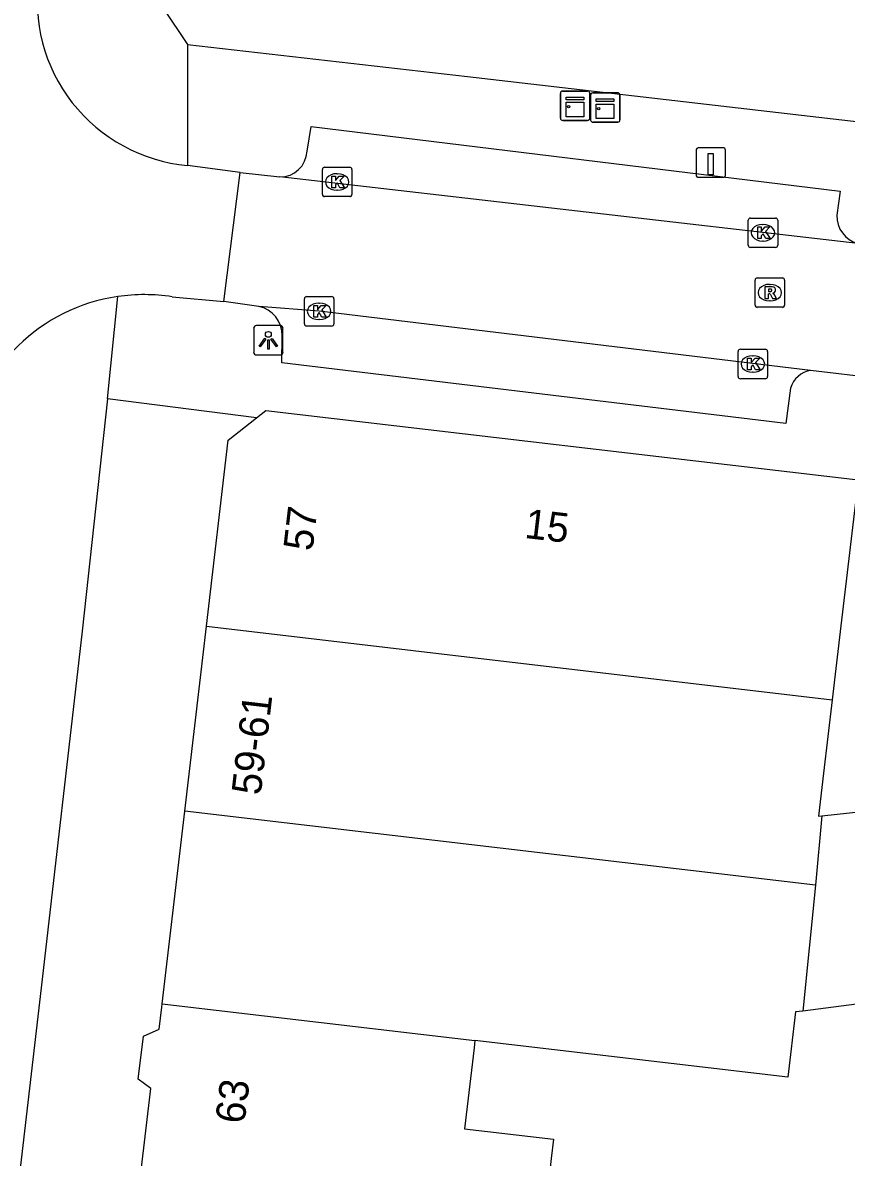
# Model space of a CAD drawing. Extents: x 162250 to 162654, y 380744 to 381605.
# Drawn here: x 162325.5 to 162353.49, y 381336.67 to 381375.24 of the extents above; entities that cross this region are included whole.
import ezdxf

# ---------------------------------------------------------------- set-up
doc = ezdxf.new("R2010")
doc.units = 0
for name, color, linetype in [('IMGEO_Kast', 7, 'Continuous'), ('IMGEO_Kolk', 7, 'Continuous'), ('IMGEO_Laadpaal', 7, 'Continuous'), ('IMGEO_Lichtpunt', 7, 'Continuous'), ('IMGEO_Pand', 7, 'Continuous'), ('IMGEO_Pand_nummerreeks', 7, 'Continuous'), ('IMGEO_Rijbaan_lokaal_open', 7, 'Continuous'), ('IMGEO_Rioolput', 7, 'Continuous'), ('IMGEO_Voetpad_open', 7, 'Continuous')]:
    doc.layers.add(name, color=color, linetype=linetype)

msp = doc.modelspace()

# ---------------------------------------------------------------- linework, layer by layer
at = {"layer": 'IMGEO_Kast'}
for p, q in [((162343.849, 381372.916), (162344.69, 381372.916)), ((162344.69, 381372.916), (162343.849, 381372.916)), ((162343.774, 381371.991), (162343.774, 381372.832)), ((162343.774, 381372.832), (162343.774, 381371.991)), ((162344.774, 381372.841), (162344.774, 381372)), ((162344.774, 381372), (162344.774, 381372.841)), ((162344.799, 381371.93), (162344.799, 381372.771)), ((162344.799, 381372.771), (162344.799, 381371.93)), ((162344.874, 381372.855), (162345.715, 381372.855)), ((162345.715, 381372.855), (162344.874, 381372.855)), ((162345.799, 381372.78), (162345.799, 381371.939)), ((162345.799, 381371.939), (162345.799, 381372.78)), ((162344.699, 381371.916), (162343.858, 381371.916)), ((162343.858, 381371.916), (162344.699, 381371.916)), ((162345.724, 381371.855), (162344.883, 381371.855)), ((162344.883, 381371.855), (162345.724, 381371.855))]:
    msp.add_line(p, q, dxfattribs=at)
for points in [[(162343.969, 381372.706), (162344.569, 381372.706), (162344.569, 381372.621), (162343.969, 381372.621), (162343.969, 381372.706)], [(162343.969, 381372.531), (162344.569, 381372.531), (162344.569, 381372.042), (162343.969, 381372.042), (162343.969, 381372.531)], [(162344.994, 381372.645), (162345.594, 381372.645), (162345.594, 381372.56), (162344.994, 381372.56), (162344.994, 381372.645)], [(162344.994, 381372.47), (162345.594, 381372.47), (162345.594, 381371.981), (162344.994, 381371.981), (162344.994, 381372.47)]]:
    msp.add_lwpolyline(points, dxfattribs=at)
for centre in [(162344.053, 381372.38), (162345.078, 381372.319)]:
    msp.add_circle(centre, 0.0377, dxfattribs=at)
for centre, start, end in [((162343.852, 381372.838), 92.4484, 184.2845), ((162343.852, 381372.838), 92.4484, 184.2845), ((162344.696, 381372.838), 2.4484, 94.2845), ((162344.696, 381372.838), 2.4484, 94.2845), ((162344.877, 381372.777), 92.4484, 184.2845), ((162344.877, 381372.777), 92.4484, 184.2845), ((162345.721, 381372.777), 2.4484, 94.2845), ((162345.721, 381372.777), 2.4484, 94.2845), ((162343.852, 381371.994), 182.4484, 274.2845), ((162343.852, 381371.994), 182.4484, 274.2845), ((162344.696, 381371.994), 272.4484, 4.2845), ((162344.696, 381371.994), 272.4484, 4.2845), ((162344.877, 381371.933), 182.4484, 274.2845), ((162344.877, 381371.933), 182.4484, 274.2845), ((162345.721, 381371.933), 272.4484, 4.2845), ((162345.721, 381371.933), 272.4484, 4.2845)]:
    msp.add_arc(centre, 0.0779, start, end, dxfattribs=at)
at = {"layer": 'IMGEO_Kolk'}
for p, q in [((162335.688, 381369.399), (162335.688, 381370.251)), ((162335.763, 381370.325), (162336.615, 381370.325)), ((162336.689, 381370.251), (162336.689, 381369.399)), ((162336.176, 381370.105), (162336.201, 381370.105)), ((162336.199, 381369.545), (162336.174, 381369.545)), ((162336.615, 381369.325), (162335.763, 381369.325)), ((162350.156, 381367.671), (162350.156, 381368.523)), ((162350.231, 381368.597), (162351.083, 381368.597)), ((162350.644, 381368.377), (162350.669, 381368.377)), ((162351.157, 381368.523), (162351.157, 381367.671)), ((162351.083, 381367.597), (162350.231, 381367.597)), ((162350.667, 381367.817), (162350.642, 381367.817)), ((162335.075, 381365.002), (162335.075, 381365.854)), ((162335.15, 381365.928), (162336.002, 381365.928)), ((162335.563, 381365.708), (162335.588, 381365.708)), ((162336.076, 381365.854), (162336.076, 381365.002)), ((162336.002, 381364.928), (162335.15, 381364.928)), ((162335.586, 381365.148), (162335.561, 381365.148)), ((162349.813, 381363.212), (162349.813, 381364.064)), ((162349.888, 381364.138), (162350.74, 381364.138)), ((162350.814, 381364.064), (162350.814, 381363.212)), ((162350.301, 381363.918), (162350.326, 381363.918)), ((162350.324, 381363.358), (162350.299, 381363.358)), ((162350.74, 381363.138), (162349.888, 381363.138))]:
    msp.add_line(p, q, dxfattribs=at)
for points in [[(162335.688, 381369.399), (162335.688, 381370.251)], [(162335.763, 381370.325), (162336.615, 381370.325)], [(162336.689, 381370.251), (162336.689, 381369.399)], [(162336.009, 381370.025), (162336.132, 381370.025), (162336.132, 381369.874), (162336.262, 381370.025), (162336.426, 381370.025), (162336.28, 381369.874), (162336.433, 381369.625), (162336.281, 381369.625), (162336.196, 381369.789), (162336.132, 381369.722), (162336.132, 381369.625), (162336.009, 381369.625), (162336.009, 381370.025)], [(162336.615, 381369.325), (162335.763, 381369.325)], [(162350.156, 381367.671), (162350.156, 381368.523)], [(162350.231, 381368.597), (162351.083, 381368.597)], [(162350.477, 381368.297), (162350.6, 381368.297), (162350.6, 381368.146), (162350.73, 381368.297), (162350.894, 381368.297), (162350.748, 381368.146), (162350.901, 381367.897), (162350.749, 381367.897), (162350.664, 381368.061), (162350.6, 381367.994), (162350.6, 381367.897), (162350.477, 381367.897), (162350.477, 381368.297)], [(162351.157, 381368.523), (162351.157, 381367.671)], [(162351.083, 381367.597), (162350.231, 381367.597)], [(162335.075, 381365.002), (162335.075, 381365.854)], [(162335.15, 381365.928), (162336.002, 381365.928)], [(162335.396, 381365.628), (162335.519, 381365.628), (162335.519, 381365.477), (162335.649, 381365.628), (162335.813, 381365.628), (162335.667, 381365.477), (162335.82, 381365.228), (162335.668, 381365.228), (162335.583, 381365.392), (162335.519, 381365.325), (162335.519, 381365.228), (162335.396, 381365.228), (162335.396, 381365.628)], [(162336.076, 381365.854), (162336.076, 381365.002)], [(162336.002, 381364.928), (162335.15, 381364.928)], [(162349.813, 381363.212), (162349.813, 381364.064)], [(162349.888, 381364.138), (162350.74, 381364.138)], [(162350.814, 381364.064), (162350.814, 381363.212)], [(162350.134, 381363.838), (162350.257, 381363.838), (162350.257, 381363.687), (162350.387, 381363.838), (162350.551, 381363.838), (162350.405, 381363.687), (162350.558, 381363.438), (162350.406, 381363.438), (162350.321, 381363.602), (162350.257, 381363.535), (162350.257, 381363.438), (162350.134, 381363.438), (162350.134, 381363.838)], [(162350.74, 381363.138), (162349.888, 381363.138)]]:
    msp.add_lwpolyline(points, dxfattribs=at)
for centre, start, end in [((162335.765, 381370.249), 91.552, 178.448), ((162335.765, 381370.249), 91.552, 178.448), ((162336.613, 381370.249), 1.552, 88.448), ((162336.613, 381370.249), 1.552, 88.448), ((162335.765, 381369.401), 181.552, 268.448), ((162335.765, 381369.401), 181.552, 268.448), ((162336.613, 381369.401), 271.552, 358.448), ((162336.613, 381369.401), 271.552, 358.448), ((162350.233, 381368.521), 91.552, 178.448), ((162350.233, 381368.521), 91.552, 178.448), ((162351.081, 381368.521), 1.552, 88.448), ((162351.081, 381368.521), 1.552, 88.448), ((162350.233, 381367.673), 181.552, 268.448), ((162350.233, 381367.673), 181.552, 268.448), ((162351.081, 381367.673), 271.552, 358.448), ((162351.081, 381367.673), 271.552, 358.448), ((162335.152, 381365.852), 91.552, 178.448), ((162335.152, 381365.852), 91.552, 178.448), ((162336, 381365.852), 1.552, 88.448), ((162336, 381365.852), 1.552, 88.448), ((162335.152, 381365.004), 181.552, 268.448), ((162335.152, 381365.004), 181.552, 268.448), ((162336, 381365.004), 271.552, 358.448), ((162336, 381365.004), 271.552, 358.448), ((162349.89, 381364.062), 91.552, 178.448), ((162349.89, 381364.062), 91.552, 178.448), ((162350.738, 381364.062), 1.552, 88.448), ((162350.738, 381364.062), 1.552, 88.448), ((162349.89, 381363.214), 181.552, 268.448), ((162349.89, 381363.214), 181.552, 268.448), ((162350.738, 381363.214), 271.552, 358.448), ((162350.738, 381363.214), 271.552, 358.448)]:
    msp.add_arc(centre, 0.0765, start, end, dxfattribs=at)
for centre, major_axis, ratio, start_param, end_param in [((162336.175, 381369.825), (-0.387, 0.002), 0.722429, 4.712389, 7.853982), ((162336.2, 381369.825), (-0.39, 0.002), 0.717154, 1.570796, 4.712389), ((162350.643, 381368.097), (-0.387, 0.002), 0.722429, 4.712389, 7.853982), ((162350.668, 381368.097), (-0.39, 0.002), 0.717154, 1.570796, 4.712389), ((162335.562, 381365.428), (-0.387, 0.002), 0.722429, 4.712389, 7.853982), ((162335.587, 381365.428), (-0.39, 0.002), 0.717154, 1.570796, 4.712389), ((162350.3, 381363.638), (-0.387, 0.002), 0.722429, 4.712389, 7.853982), ((162350.325, 381363.638), (-0.39, 0.002), 0.717154, 1.570796, 4.712389)]:
    msp.add_ellipse(centre, major_axis=major_axis, ratio=ratio, start_param=start_param, end_param=end_param, dxfattribs=at)
at = {"layer": 'IMGEO_Laadpaal'}
for p, q in [((162349.301, 381370.984), (162348.46, 381370.984)), ((162349.301, 381370.984), (162348.46, 381370.984)), ((162348.385, 381370.9), (162348.385, 381370.059)), ((162348.385, 381370.9), (162348.385, 381370.059)), ((162349.385, 381370.068), (162349.385, 381370.909)), ((162349.385, 381370.068), (162349.385, 381370.909)), ((162348.469, 381369.984), (162349.31, 381369.984)), ((162348.469, 381369.984), (162349.31, 381369.984))]:
    msp.add_line(p, q, dxfattribs=at)
msp.add_lwpolyline([(162348.8, 381370.797), (162348.96, 381370.797), (162348.96, 381370.064), (162348.8, 381370.064), (162348.8, 381370.797)], dxfattribs=at)
for centre, start, end in [((162348.463, 381370.906), 92.4484, 184.2845), ((162348.463, 381370.906), 92.4484, 184.2845), ((162349.307, 381370.906), 2.4484, 94.2845), ((162349.307, 381370.906), 2.4484, 94.2845), ((162348.463, 381370.062), 182.4484, 274.2845), ((162348.463, 381370.062), 182.4484, 274.2845), ((162349.307, 381370.062), 272.4484, 4.2845), ((162349.307, 381370.062), 272.4484, 4.2845)]:
    msp.add_arc(centre, 0.0779, start, end, dxfattribs=at)
at = {"layer": 'IMGEO_Lichtpunt'}
for p, q in [((162333.352, 381364.846), (162333.352, 381364.039)), ((162333.352, 381364.846), (162333.352, 381364.039)), ((162334.254, 381364.941), (162333.446, 381364.941)), ((162334.254, 381364.941), (162333.446, 381364.941)), ((162334.348, 381364.039), (162334.348, 381364.846)), ((162334.348, 381364.039), (162334.348, 381364.846)), ((162333.446, 381363.945), (162334.254, 381363.945)), ((162333.446, 381363.945), (162334.254, 381363.945))]:
    msp.add_line(p, q, dxfattribs=at)
for points in [[(162333.726, 381364.51), (162333.765, 381364.482), (162333.577, 381364.22), (162333.539, 381364.247), (162333.726, 381364.51)], [(162333.828, 381364.462), (162333.875, 381364.462), (162333.875, 381364.14), (162333.828, 381364.14), (162333.828, 381364.462)], [(162333.938, 381364.482), (162333.976, 381364.509), (162334.163, 381364.247), (162334.124, 381364.219), (162333.938, 381364.482)]]:
    msp.add_lwpolyline(points, dxfattribs=at)
msp.add_circle((162333.851, 381364.644), 0.0994, dxfattribs=at)
for centre, start, end in [((162333.446, 381364.846), 90, 180), ((162333.446, 381364.846), 90, 180), ((162334.254, 381364.846), 0, 90), ((162334.254, 381364.846), 0, 90), ((162333.446, 381364.039), 180, 270), ((162333.446, 381364.039), 180, 270), ((162334.254, 381364.039), 270, 0), ((162334.254, 381364.039), 270, 360)]:
    msp.add_arc(centre, 0.0946, start, end, dxfattribs=at)
at = {"layer": 'IMGEO_Pand'}
for points in [[(162331.749, 381354.725), (162332.491, 381361.05), (162333.445, 381361.804)], [(162333.445, 381361.804), (162333.767, 381362.058), (162353.887, 381359.698)], [(162353.887, 381359.698), (162353.305, 381354.733), (162353.011, 381352.227)], [(162331.011, 381348.438), (162331.669, 381354.046), (162331.704, 381354.344), (162331.749, 381354.725)], [(162331.749, 381354.725), (162353.011, 381352.227)], [(162353.011, 381352.227), (162352.718, 381349.727), (162352.546, 381348.266), (162352.656, 381348.278)], [(162352.656, 381348.278), (162356.414, 381348.684), (162356.796, 381345.146), (162357.009, 381345.169), (162357.316, 381342.327), (162352.007, 381341.645)], [(162330.243, 381341.891), (162331.011, 381348.438)], [(162352.444, 381345.925), (162331.011, 381348.438)], [(162352.656, 381348.278), (162352.444, 381345.925)], [(162352.444, 381345.925), (162352.007, 381341.645)], [(162340.872, 381340.643), (162340.843, 381340.397), (162340.52, 381337.645), (162343.543, 381337.291), (162343.465, 381336.631), (162343.226, 381334.524), (162334.488, 381335.549), (162329.522, 381336.131), (162329.86, 381339.014), (162329.432, 381339.332), (162329.603, 381340.791), (162330.142, 381341.023), (162330.23, 381341.78), (162330.243, 381341.891)], [(162330.243, 381341.891), (162340.872, 381340.643)], [(162352.007, 381341.645), (162351.764, 381341.614), (162351.504, 381339.396), (162340.872, 381340.643)]]:
    msp.add_lwpolyline(points, dxfattribs=at)
at = {"layer": 'IMGEO_Rijbaan_lokaal_open'}
for points in [[(162332.888, 381370.148), (162331.099, 381370.386)], [(162332.334, 381365.76), (162332.888, 381370.148)], [(162332.888, 381370.148), (162334.237, 381369.996)], [(162353.883, 381367.738), (162334.237, 381369.996)], [(162330.579, 381365.92), (162332.334, 381365.76)], [(162333.525, 381365.596), (162332.334, 381365.76)], [(162352.274, 381363.417), (162335.576, 381365.429), (162333.525, 381365.596)], [(162354.574, 381363.147), (162352.274, 381363.417)]]:
    msp.add_lwpolyline(points, dxfattribs=at)
for centre, radius, start, end in [((162331.617, 381375.985), 5.623, 171.3899, 264.7176), ((162329.623, 381359.875), 6.12, 81.0159, 98.3634), ((162329.623, 381359.869), 6.126, 98.35, 170.1613)]:
    msp.add_arc(centre, radius, start, end, dxfattribs=at)
at = {"layer": 'IMGEO_Rioolput'}
for p, q in [((162350.389, 381365.637), (162350.389, 381366.489)), ((162350.464, 381366.563), (162351.316, 381366.563)), ((162350.877, 381366.343), (162350.902, 381366.343)), ((162351.39, 381366.489), (162351.39, 381365.637)), ((162351.316, 381365.563), (162350.464, 381365.563)), ((162350.9, 381365.783), (162350.875, 381365.783))]:
    msp.add_line(p, q, dxfattribs=at)
for points in [[(162350.389, 381365.637), (162350.389, 381366.489)], [(162350.464, 381366.563), (162351.316, 381366.563)], [(162351.39, 381366.489), (162351.39, 381365.637)], [(162350.978, 381366.261), (162350.726, 381366.263), (162350.726, 381365.863)], [(162350.726, 381365.863), (162350.85, 381365.863), (162350.85, 381366.025), (162350.861, 381366.025)], [(162350.904, 381366.182), (162350.85, 381366.182), (162350.85, 381366.101)], [(162350.85, 381366.101), (162350.902, 381366.101)], [(162350.908, 381365.996), (162350.979, 381365.863), (162351.119, 381365.863), (162351.054, 381365.989)], [(162351.316, 381365.563), (162350.464, 381365.563)]]:
    msp.add_lwpolyline(points, dxfattribs=at)
for centre, radius, start, end in [((162350.466, 381366.487), 0.0765, 91.552, 178.448), ((162350.466, 381366.487), 0.0765, 91.552, 178.448), ((162351.314, 381366.487), 0.0765, 1.552, 88.448), ((162351.314, 381366.487), 0.0765, 1.552, 88.448), ((162350.86, 381365.972), 0.0533, 26.0293, 88.6989), ((162350.886, 381366.29), 0.19, 274.7715, 282.9687), ((162350.91, 381366.086), 0.0964, 77.0061, 93.1865), ((162350.924, 381366.143), 0.0378, 276.6634, 79.6772), ((162350.977, 381366.151), 0.109, 350.3612, 89.416), ((162350.975, 381366.151), 0.112, 277.5842, 350.9817), ((162350.959, 381365.936), 0.108, 29.5134, 73.7905), ((162350.466, 381365.639), 0.0765, 181.552, 268.448), ((162350.466, 381365.639), 0.0765, 181.552, 268.448), ((162351.314, 381365.639), 0.0765, 271.552, 358.448), ((162351.314, 381365.639), 0.0765, 271.552, 358.448)]:
    msp.add_arc(centre, radius, start, end, dxfattribs=at)
for centre, major_axis, ratio, start_param, end_param in [((162350.876, 381366.063), (-0.387, 0.002), 0.722429, 4.712389, 7.853982), ((162350.901, 381366.063), (-0.39, 0.002), 0.717154, 1.570796, 4.712389)]:
    msp.add_ellipse(centre, major_axis=major_axis, ratio=ratio, start_param=start_param, end_param=end_param, dxfattribs=at)
at = {"layer": 'IMGEO_Voetpad_open'}
for points in [[(162334.576, 381404.093), (162332.211, 381387.945), (162332.068, 381387.938), (162330.281, 381375.735), (162331.101, 381374.491)], [(162331.101, 381374.491), (162331.099, 381370.386)], [(162331.101, 381374.491), (162340.622, 381373.413), (162412.338, 381365.108), (162424.743, 381363.694)], [(162335.166, 381370.874), (162335.305, 381371.705), (162353.278, 381369.51), (162353.17, 381368.697)], [(162328.382, 381362.452), (162328.733, 381365.93)], [(162351.591, 381362.82), (162351.43, 381361.612), (162334.304, 381363.671), (162334.323, 381364.598)], [(162328.382, 381362.452), (162327.527, 381354.554), (162326.13, 381342.433), (162314.082, 381238.883)], [(162333.445, 381361.804), (162328.382, 381362.452)]]:
    msp.add_lwpolyline(points, dxfattribs=at)
for centre, radius, start, end in [((162334.251, 381370.912), 0.916, 269.1147, 357.6519), ((162354.111, 381368.652), 0.942, 177.2703, 255.9901), ((162333.308, 381364.604), 1.015, 359.6383, 77.6533), ((162352.421, 381362.56), 0.87, 99.7324, 162.58)]:
    msp.add_arc(centre, radius, start, end, dxfattribs=at)

# ---------------------------------------------------------------- texts
at = {"layer": 'IMGEO_Pand_nummerreeks'}
for s, rotation, p in [('57', 83.3089, (162335.349, 381357.256)), ('15', 353.31, (162342.53, 381357.728)), ('59-61', 83.3081, (162333.589, 381348.956)), ('63', 82.8669, (162333.035, 381337.784))]:
    msp.add_text(s, height=1, rotation=rotation, dxfattribs=at).set_placement(p)

doc.saveas('drawing.dxf')
